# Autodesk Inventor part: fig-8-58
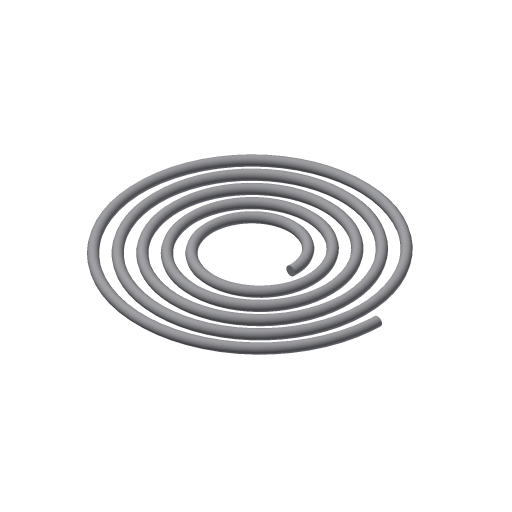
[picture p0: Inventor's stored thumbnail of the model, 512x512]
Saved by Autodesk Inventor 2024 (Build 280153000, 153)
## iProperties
Shininess: 77.0
Length Units: 11269
Angle Units: 11279
Time Units: 11290
Mass Units: 11283
Length Display Precision: 3
Angle Display Precision: 2
Created: 2002-01
Part Number: fig-8-58
Document SubType Name: Modeling
Designer: CADSoft
Density: 1 g/cm^3
Material: Generic
Appearance: Default
Density: 0.0
Volumn: 0.0
Area: 0.0
PropertySet Name: Model Information
Control State: 0
Master: False
Checked Out: False
Author: CADSoft
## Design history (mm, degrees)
sketch "Sketch2"
  geometry: C1 r 2.5 at (-19.895, -0.092)
  constraints: 1 centre point
  dimensions: "d0" = 5 diameter of C1
coil "Coil5" sketch "Sketch2" pitch "d35" = 10; turns "d37" = 5; dims "d36" = 10, "d38" = 0, angle "d39" = 90 deg, angle "d40" = 90 deg, "d41" = 0, "d42" = 0
body "Solid1"
